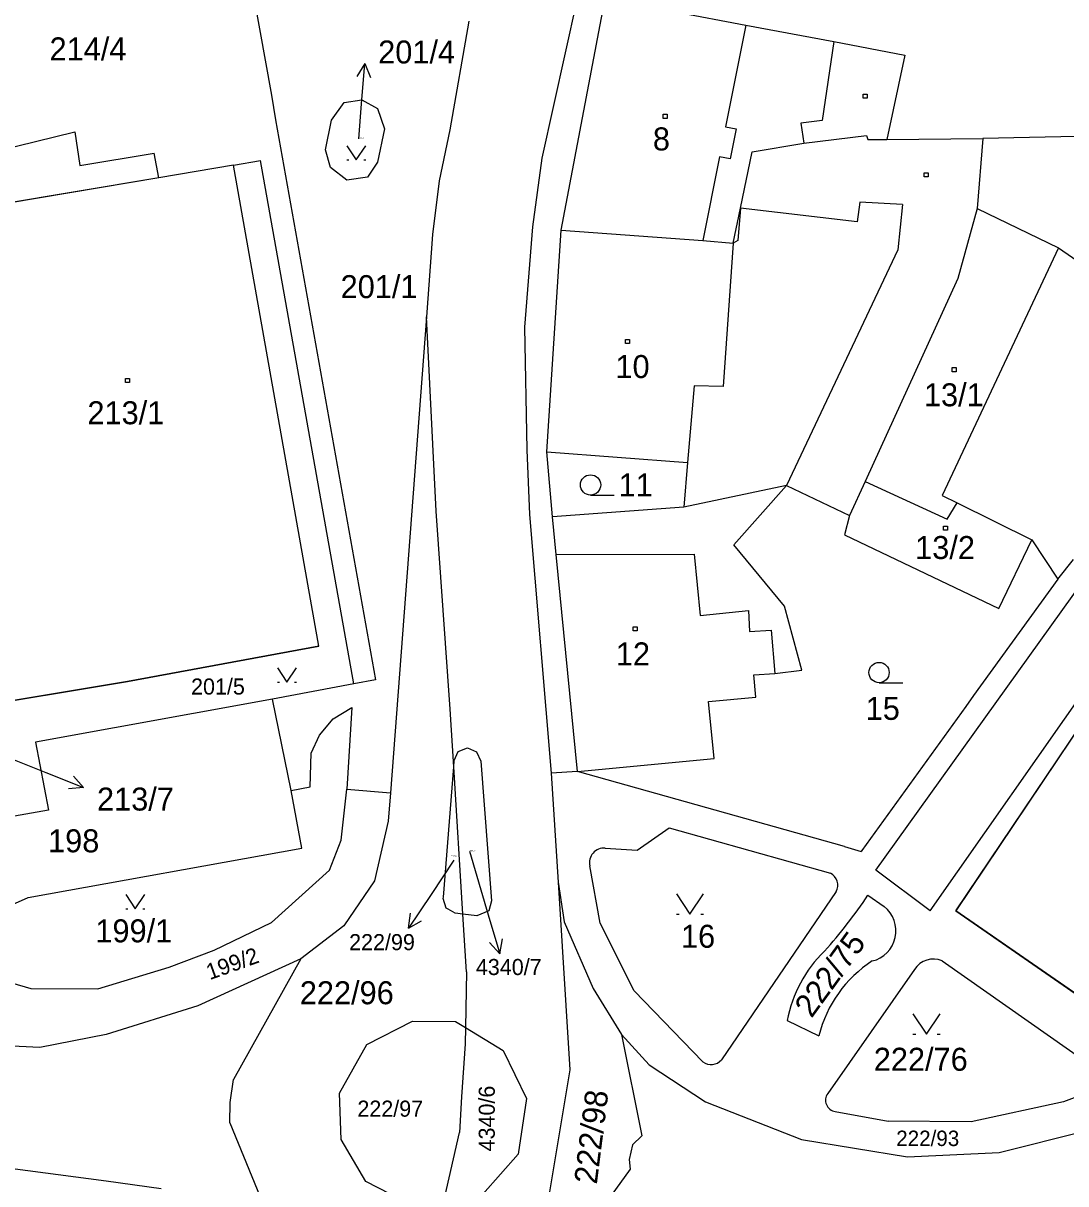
# Model space of a CAD drawing. Extents: x -468021 to -466942, y -1130484 to -1128584.
# Drawn here: x -467492.3 to -467415.1, y -1129055.3 to -1128969.4 of the extents above; entities that cross this region are included whole.
import ezdxf

# ---------------------------------------------------------------- set-up
doc = ezdxf.new("R2010")
doc.units = 0
for name, color, linetype in [('19-PK-šrafy', 7, 'Continuous'), ('22-Odběrná místa-šrafy', 7, 'Continuous'), ('DKM', 7, 'Continuous')]:
    doc.layers.add(name, color=color, linetype=linetype)

msp = doc.modelspace()

# ---------------------------------------------------------------- linework, layer by layer
at = {"layer": '19-PK-šrafy'}
msp.add_lwpolyline([(-467399.25, -1129024.07), (-467400.13, -1129023.43), (-467410.43, -1129016.03), (-467423.26, -1129035.1), (-467412.19, -1129042.78), (-467399.25, -1129024.07)], dxfattribs=at)
at = {"layer": '22-Odběrná místa-šrafy'}
msp.add_lwpolyline([(-467512.86, -1129016.55), (-467503.64, -1129015.36), (-467503.25, -1129018.31), (-467503.09, -1129019.57), (-467497.18, -1129018.69), (-467496.9, -1129020.2), (-467484.57, -1129018.14), (-467470.42, -1129015.53), (-467476.73, -1128979.94), (-467482.25, -1128980.87), (-467497.8, -1128983.49), (-467504.8, -1128984.67), (-467508.2, -1128985.12), (-467508.09, -1128985.96), (-467516.57, -1128987.04), (-467515.48, -1128993.37), (-467516.56, -1128993.53)], close=True, dxfattribs=at)
at = {"layer": 'DKM'}
for p, q in [((-467475.84, -1128964.15), (-467473.92, -1128974.77)), ((-467451.33, -1128967.74), (-467453.9, -1128979.43)), ((-467452.49, -1128984.74), (-467449.21, -1128967.58)), ((-467449.21, -1128967.58), (-467438.81, -1128969.59)), ((-467459.31, -1128969.29), (-467460.71, -1128977.34)), ((-467438.81, -1128969.59), (-467440.31, -1128977.11)), ((-467438.81, -1128969.59), (-467432.3, -1128970.79)), ((-467432.3, -1128970.79), (-467433.17, -1128976.65)), ((-467432.3, -1128970.79), (-467427.04, -1128971.8)), ((-467467.019, -1128972.418), (-467467.594, -1128973.377)), ((-467467.25, -1128975.41), (-467467.019, -1128972.418)), ((-467467.019, -1128972.418), (-467466.597, -1128973.454)), ((-467427.04, -1128971.8), (-467428.37, -1128978.04)), ((-467473.92, -1128974.77), (-467473.62, -1128976.6)), ((-467430.13, -1128974.68), (-467429.83, -1128974.68)), ((-467430.13, -1128974.98), (-467430.13, -1128974.68)), ((-467429.83, -1128974.98), (-467430.13, -1128974.98)), ((-467429.83, -1128974.68), (-467429.83, -1128974.98)), ((-467469.48, -1128976.61), (-467468.54, -1128975.31)), ((-467468.54, -1128975.31), (-467467.22, -1128975.1)), ((-467467.45, -1128977.99), (-467467.25, -1128975.41)), ((-467467.22, -1128975.1), (-467466.08, -1128975.74)), ((-467466.08, -1128975.74), (-467465.56, -1128977.25)), ((-467473.62, -1128976.6), (-467466.23, -1129018.01)), ((-467469.93, -1128978.8), (-467469.48, -1128976.61)), ((-467444.93, -1128976.18), (-467444.63, -1128976.18)), ((-467444.93, -1128976.48), (-467444.93, -1128976.18)), ((-467444.63, -1128976.48), (-467444.93, -1128976.48)), ((-467444.63, -1128976.18), (-467444.63, -1128976.48)), ((-467433.17, -1128976.65), (-467434.74, -1128976.83)), ((-467498.32, -1128979.89), (-467488.47, -1128977.47)), ((-467488.47, -1128977.47), (-467488.11, -1128979.96)), ((-467465.56, -1128977.25), (-467466.06, -1128979.71)), ((-467460.71, -1128977.34), (-467461.5, -1128981.11)), ((-467440.31, -1128977.11), (-467439.53, -1128977.26)), ((-467439.53, -1128977.26), (-467439.96, -1128979.48)), ((-467434.74, -1128976.83), (-467434.51, -1128978.32)), ((-467438.34, -1128978.96), (-467434.51, -1128978.32)), ((-467434.51, -1128978.32), (-467429.88, -1128977.75)), ((-467429.88, -1128977.75), (-467429.78, -1128978.05)), ((-467429.78, -1128978.05), (-467428.37, -1128978.04)), ((-467428.37, -1128978.04), (-467421.28, -1128977.96)), ((-467421.28, -1128977.96), (-467421.69, -1128983.15)), ((-467409.89, -1128977.74), (-467421.28, -1128977.96)), ((-467488.11, -1128979.96), (-467482.61, -1128979.06)), ((-467482.25, -1128980.87), (-467482.61, -1128979.06)), ((-467469.56, -1128980.11), (-467469.93, -1128978.8)), ((-467468.34, -1128978.51), (-467467.64, -1128979.56)), ((-467467.64, -1128979.56), (-467466.94, -1128978.51)), ((-467440.75, -1128979.32), (-467441.99, -1128985.51)), ((-467439.96, -1128979.48), (-467440.75, -1128979.32)), ((-467439.21, -1128983.12), (-467438.34, -1128978.96)), ((-467476.73, -1128979.94), (-467482.25, -1128980.87)), ((-467476.73, -1128979.94), (-467474.72, -1128979.6)), ((-467470.42, -1129015.53), (-467476.73, -1128979.94)), ((-467467.83, -1129018.31), (-467474.72, -1128979.6)), ((-467468.33, -1128981.05), (-467469.56, -1128980.11)), ((-467468.34, -1128979.56), (-467468.2, -1128979.56)), ((-467467.08, -1128979.56), (-467466.94, -1128979.56)), ((-467466.06, -1128979.71), (-467466.82, -1128980.83)), ((-467453.9, -1128979.43), (-467454.61, -1128984.51)), ((-467482.25, -1128980.87), (-467497.8, -1128983.49)), ((-467466.82, -1128980.83), (-467468.33, -1128981.05)), ((-467425.61, -1128980.51), (-467425.31, -1128980.51)), ((-467425.61, -1128980.81), (-467425.61, -1128980.51)), ((-467425.31, -1128980.81), (-467425.61, -1128980.81)), ((-467425.31, -1128980.51), (-467425.31, -1128980.81)), ((-467461.5, -1128981.11), (-467462, -1128985.08)), ((-467430.38, -1128982.69), (-467430.56, -1128984.13)), ((-467427.21, -1128982.86), (-467430.38, -1128982.69)), ((-467439.76, -1128985.72), (-467439.21, -1128983.12)), ((-467439.21, -1128983.12), (-467439.41, -1128985.52)), ((-467430.56, -1128984.13), (-467439.21, -1128983.12)), ((-467427.21, -1128982.86), (-467427.57, -1128986.2)), ((-467421.69, -1128983.15), (-467423.11, -1128988.33)), ((-467421.69, -1128983.15), (-467415.68, -1128986.06)), ((-467462, -1128985.08), (-467462.45, -1128991.16)), ((-467454.61, -1128984.51), (-467455.19, -1128991.92)), ((-467453.53, -1129001.16), (-467452.49, -1128984.74)), ((-467452.49, -1128984.74), (-467441.99, -1128985.51)), ((-467441.99, -1128985.51), (-467439.76, -1128985.72)), ((-467439.76, -1128985.72), (-467440.5, -1128996.32)), ((-467439.41, -1128985.52), (-467439.76, -1128985.72)), ((-467427.57, -1128986.2), (-467435.8, -1129003.63)), ((-467415.68, -1128986.06), (-467424.29, -1129004.37)), ((-467415.68, -1128986.06), (-467403.02, -1128994.78)), ((-467423.11, -1128988.33), (-467429.99, -1129003.34)), ((-467462.45, -1128991.16), (-467465.11, -1129026.37)), ((-467461.73, -1129005.55), (-467462.45, -1128991.16)), ((-467455.19, -1128991.92), (-467455.03, -1129001)), ((-467447.71, -1128992.83), (-467447.41, -1128992.83)), ((-467447.71, -1128993.13), (-467447.71, -1128992.83)), ((-467447.41, -1128992.83), (-467447.41, -1128993.13)), ((-467447.41, -1128993.13), (-467447.71, -1128993.13)), ((-467423.54, -1128994.92), (-467423.24, -1128994.92)), ((-467423.54, -1128995.22), (-467423.54, -1128994.92)), ((-467423.24, -1128995.22), (-467423.54, -1128995.22)), ((-467423.24, -1128994.92), (-467423.24, -1128995.22)), ((-467484.72, -1128995.73), (-467484.42, -1128995.73)), ((-467484.72, -1128996.03), (-467484.72, -1128995.73)), ((-467484.42, -1128996.03), (-467484.72, -1128996.03)), ((-467484.42, -1128995.73), (-467484.42, -1128996.03)), ((-467442.63, -1128996.26), (-467443.12, -1129001.94)), ((-467440.5, -1128996.32), (-467442.63, -1128996.26)), ((-467455.03, -1129001), (-467454.83, -1129005.78)), ((-467453.53, -1129001.16), (-467443.12, -1129001.94)), ((-467453.11, -1129005.96), (-467453.53, -1129001.16)), ((-467443.12, -1129001.94), (-467443.41, -1129005.24)), ((-467429.99, -1129003.34), (-467431.14, -1129005.85)), ((-467429.99, -1129003.34), (-467423.9, -1129006.13)), ((-467435.8, -1129003.63), (-467443.41, -1129005.24)), ((-467439.71, -1129008.02), (-467435.8, -1129003.63)), ((-467435.8, -1129003.63), (-467431.14, -1129005.85)), ((-467450.3, -1129004.35), (-467448.55, -1129004.35)), ((-467424.29, -1129004.37), (-467423.17, -1129004.92)), ((-467423.9, -1129006.13), (-467423.17, -1129004.92)), ((-467423.17, -1129004.92), (-467417.64, -1129007.65)), ((-467460.69, -1129020.19), (-467461.73, -1129005.55)), ((-467454.83, -1129005.78), (-467453.22, -1129024.92)), ((-467443.41, -1129005.24), (-467453.11, -1129005.96)), ((-467452.84, -1129008.75), (-467453.11, -1129005.96)), ((-467431.14, -1129005.85), (-467431.5, -1129007.29)), ((-467424.18, -1129006.64), (-467423.88, -1129006.64)), ((-467424.18, -1129006.94), (-467424.18, -1129006.64)), ((-467423.88, -1129006.64), (-467423.88, -1129006.94)), ((-467431.5, -1129007.29), (-467420.09, -1129012.74)), ((-467423.88, -1129006.94), (-467424.18, -1129006.94)), ((-467420.09, -1129012.74), (-467417.64, -1129007.65)), ((-467417.64, -1129007.65), (-467415.73, -1129010.56)), ((-467435.94, -1129012.58), (-467439.71, -1129008.02)), ((-467452.84, -1129008.75), (-467442.63, -1129008.71)), ((-467451.28, -1129024.81), (-467452.84, -1129008.75)), ((-467442.63, -1129008.71), (-467442.19, -1129013.26)), ((-467415.73, -1129010.56), (-467414.57, -1129009.12)), ((-467429.2, -1129032.11), (-467413.85, -1129010.73)), ((-467415.73, -1129010.56), (-467421.96, -1129019.19)), ((-467434.66, -1129017.31), (-467435.94, -1129012.58)), ((-467442.19, -1129013.26), (-467438.61, -1129012.89)), ((-467438.61, -1129012.89), (-467438.53, -1129014.45)), ((-467447.15, -1129014.09), (-467446.85, -1129014.09)), ((-467447.15, -1129014.39), (-467447.15, -1129014.09)), ((-467446.85, -1129014.39), (-467447.15, -1129014.39)), ((-467446.85, -1129014.09), (-467446.85, -1129014.39)), ((-467438.53, -1129014.45), (-467436.93, -1129014.35)), ((-467436.93, -1129014.35), (-467436.67, -1129017.55)), ((-467470.42, -1129015.53), (-467484.57, -1129018.14)), ((-467425.18, -1129035.1), (-467411.44, -1129015.51)), ((-467423.26, -1129035.1), (-467410.43, -1129016.03)), ((-467473.47, -1129017.14), (-467472.77, -1129018.19)), ((-467472.77, -1129018.19), (-467472.07, -1129017.14)), ((-467438.22, -1129017.65), (-467436.67, -1129017.55)), ((-467438.06, -1129019.29), (-467438.22, -1129017.65)), ((-467436.67, -1129017.55), (-467434.66, -1129017.31)), ((-467484.57, -1129018.14), (-467496.9, -1129020.2)), ((-467467.83, -1129018.31), (-467473.83, -1129019.44)), ((-467473.47, -1129018.19), (-467473.33, -1129018.19)), ((-467472.21, -1129018.19), (-467472.07, -1129018.19)), ((-467466.23, -1129018.01), (-467467.83, -1129018.31)), ((-467428.95, -1129018.23), (-467427.2, -1129018.23)), ((-467473.83, -1129019.44), (-467491.39, -1129022.64)), ((-467472.47, -1129026.21), (-467473.83, -1129019.44)), ((-467441.57, -1129019.63), (-467438.06, -1129019.29)), ((-467441.16, -1129023.83), (-467441.57, -1129019.63)), ((-467421.96, -1129019.19), (-467422.54, -1129020)), ((-467469.35, -1129020.91), (-467467.97, -1129020.06)), ((-467467.97, -1129020.06), (-467468.35, -1129026.12)), ((-467460.43, -1129024.45), (-467460.69, -1129020.19)), ((-467422.54, -1129020), (-467430.22, -1129030.64)), ((-467470.37, -1129022.11), (-467469.35, -1129020.91)), ((-467470.97, -1129023.45), (-467470.37, -1129022.11)), ((-467495.16, -1129023.07), (-467490.62, -1129024.88)), ((-467491.39, -1129022.64), (-467490.42, -1129027.65)), ((-467460.09, -1129023.33), (-467459.4, -1129023.06)), ((-467459.4, -1129023.06), (-467458.75, -1129023.34)), ((-467471.05, -1129025.94), (-467470.97, -1129023.45)), ((-467460.43, -1129024.45), (-467460.39, -1129023.98)), ((-467460.39, -1129023.98), (-467460.09, -1129023.33)), ((-467458.75, -1129023.34), (-467458.43, -1129024.04)), ((-467451.28, -1129024.81), (-467441.16, -1129023.83)), ((-467461.19, -1129034.1), (-467460.43, -1129024.45)), ((-467459.75, -1129035.35), (-467460.43, -1129024.45)), ((-467458.43, -1129024.04), (-467457.63, -1129034.38)), ((-467451.28, -1129024.81), (-467453.22, -1129024.92)), ((-467431.52, -1129030.35), (-467451.28, -1129024.81)), ((-467490.62, -1129024.88), (-467487.833, -1129025.99)), ((-467487.833, -1129025.99), (-467488.576, -1129025.155)), ((-467453.22, -1129024.92), (-467452.71, -1129033)), ((-467487.833, -1129025.99), (-467488.947, -1129026.084)), ((-467472.47, -1129026.21), (-467471.05, -1129025.94)), ((-467471.68, -1129030.48), (-467472.47, -1129026.21)), ((-467468.75, -1129029.87), (-467468.35, -1129026.12)), ((-467468.35, -1129026.12), (-467465.11, -1129026.37)), ((-467465.11, -1129026.37), (-467465.27, -1129028.48)), ((-467490.42, -1129027.65), (-467494.46, -1129028.36)), ((-467465.27, -1129028.48), (-467466.29, -1129032.89)), ((-467446.85, -1129030.61), (-467444.48, -1129028.96)), ((-467444.48, -1129028.96), (-467432.55, -1129032.33)), ((-467469.62, -1129032.11), (-467468.75, -1129029.87)), ((-467491.93, -1129034.13), (-467471.68, -1129030.48)), ((-467459.25, -1129030.7), (-467457.87, -1129035.4)), ((-467449.21, -1129030.48), (-467446.85, -1129030.61)), ((-467431.52, -1129030.35), (-467430.28, -1129030.73)), ((-467430.22, -1129030.64), (-467430.28, -1129030.73)), ((-467460.42, -1129031.37), (-467462.11, -1129033.9)), ((-467473.92, -1129035.96), (-467469.62, -1129032.11)), ((-467449.58, -1129036.01), (-467450.35, -1129031.79)), ((-467425.18, -1129035.1), (-467429.2, -1129032.11)), ((-467466.29, -1129032.89), (-467468.57, -1129036.23)), ((-467452.71, -1129033), (-467451.84, -1129046.87)), ((-467452.71, -1129033), (-467452.25, -1129035.92)), ((-467495.6, -1129035.76), (-467491.93, -1129034.13)), ((-467484.7, -1129033.91), (-467484, -1129034.96)), ((-467484, -1129034.96), (-467483.3, -1129033.91)), ((-467462.11, -1129033.9), (-467463.778, -1129036.393)), ((-467461.2, -1129034.2), (-467461.19, -1129034.1)), ((-467460.99, -1129034.9), (-467461.2, -1129034.2)), ((-467443.95, -1129033.85), (-467442.95, -1129035.35)), ((-467442.95, -1129035.35), (-467441.95, -1129033.85)), ((-467432.13, -1129033.69), (-467440.61, -1129046.13)), ((-467429.77, -1129033.95), (-467428.57, -1129034.8)), ((-467484.7, -1129034.96), (-467484.56, -1129034.96)), ((-467483.44, -1129034.96), (-467483.3, -1129034.96)), ((-467460.85, -1129034.98), (-467460.99, -1129034.9)), ((-467460.33, -1129035.27), (-467460.85, -1129034.98)), ((-467457.83, -1129035.12), (-467458.72, -1129035.48)), ((-467457.63, -1129034.38), (-467457.83, -1129035.12)), ((-467412.19, -1129042.78), (-467423.26, -1129035.1)), ((-467478.17, -1129038.02), (-467473.92, -1129035.96)), ((-467463.778, -1129036.393), (-467463.637, -1129035.283)), ((-467463.778, -1129036.393), (-467462.806, -1129035.84)), ((-467459.75, -1129035.35), (-467460.33, -1129035.27)), ((-467458.72, -1129035.48), (-467459.75, -1129035.35)), ((-467459.49, -1129039.62), (-467459.75, -1129035.35)), ((-467457.87, -1129035.4), (-467457.026, -1129038.279)), ((-467452.25, -1129035.92), (-467450.11, -1129040.85)), ((-467447.07, -1129041.03), (-467449.58, -1129036.01)), ((-467443.95, -1129035.35), (-467443.75, -1129035.35)), ((-467442.15, -1129035.35), (-467441.95, -1129035.35)), ((-467468.57, -1129036.23), (-467471.74, -1129038.65)), ((-467457.026, -1129038.279), (-467457.787, -1129037.459)), ((-467457.026, -1129038.279), (-467456.828, -1129037.178)), ((-467481.49, -1129039.28), (-467478.17, -1129038.02)), ((-467497.27, -1129039.25), (-467491.74, -1129040.85)), ((-467486.78, -1129040.89), (-467481.49, -1129039.28)), ((-467471.74, -1129038.65), (-467479.37, -1129042.13)), ((-467471.74, -1129038.65), (-467476.73, -1129047.58)), ((-467426.32, -1129039.46), (-467432.75, -1129048.63)), ((-467424.28, -1129038.81), (-467411.49, -1129047.8)), ((-467459.49, -1129039.62), (-467459.57, -1129043.75)), ((-467491.74, -1129040.85), (-467486.78, -1129040.89)), ((-467450.11, -1129040.85), (-467448.02, -1129044.25)), ((-467441.99, -1129046.27), (-467447.07, -1129041.03)), ((-467479.37, -1129042.13), (-467486.14, -1129044.25)), ((-467426.44, -1129042.74), (-467425.44, -1129044.24)), ((-467425.44, -1129044.24), (-467424.44, -1129042.74)), ((-467466.86, -1129045), (-467463.47, -1129043.26)), ((-467463.47, -1129043.26), (-467460.3, -1129043.3)), ((-467460.3, -1129043.3), (-467459.57, -1129043.75)), ((-467459.57, -1129043.75), (-467459.59, -1129044.94)), ((-467459.57, -1129043.75), (-467456.78, -1129045.45)), ((-467435.75, -1129043.23), (-467433.4, -1129044.36)), ((-467486.14, -1129044.25), (-467491.07, -1129045.23)), ((-467448.02, -1129044.25), (-467445.96, -1129046.51)), ((-467448.02, -1129044.25), (-467446.5, -1129051.75)), ((-467426.44, -1129044.24), (-467426.24, -1129044.24)), ((-467424.64, -1129044.24), (-467424.44, -1129044.24)), ((-467491.07, -1129045.23), (-467493.61, -1129045.09)), ((-467468.89, -1129048.6), (-467466.86, -1129045)), ((-467459.59, -1129044.94), (-467459.86, -1129048.87)), ((-467456.78, -1129045.45), (-467455.04, -1129048.99)), ((-467451.84, -1129046.87), (-467454.66, -1129063.71)), ((-467445.96, -1129046.51), (-467441.79, -1129049.24)), ((-467476.97, -1129049.29), (-467476.73, -1129047.58)), ((-467411.49, -1129047.8), (-467415.3, -1129049.24)), ((-467468.77, -1129052.02), (-467468.89, -1129048.6)), ((-467459.86, -1129048.87), (-467460, -1129051.5)), ((-467476.99, -1129050.8), (-467476.97, -1129049.29)), ((-467455.04, -1129048.99), (-467455.65, -1129053.11)), ((-467441.79, -1129049.24), (-467434.7, -1129052.03)), ((-467415.3, -1129049.24), (-467422.14, -1129050.72)), ((-467432.2, -1129049.96), (-467428.27, -1129050.68)), ((-467476.99, -1129050.8), (-467473.5, -1129059.29)), ((-467422.14, -1129050.72), (-467428.27, -1129050.68)), ((-467420.07, -1129052.99), (-467413.77, -1129051.4)), ((-467486.14, -1129055.12), (-467508.06, -1129052.24)), ((-467466.94, -1129055.14), (-467468.77, -1129052.02)), ((-467461.22, -1129056.82), (-467460, -1129051.5)), ((-467446.5, -1129051.75), (-467447.21, -1129052.43)), ((-467434.7, -1129052.03), (-467426.84, -1129053.32)), ((-467455.65, -1129053.11), (-467458.27, -1129056.06)), ((-467447.21, -1129052.43), (-467447.45, -1129053.51)), ((-467426.84, -1129053.32), (-467420.07, -1129052.99)), ((-467447.45, -1129053.51), (-467447.36, -1129054.22)), ((-467447.36, -1129054.22), (-467453.09, -1129062.13)), ((-467482.08, -1129055.67), (-467486.14, -1129055.12)), ((-467463.24, -1129057.03), (-467466.94, -1129055.14))]:
    msp.add_line(p, q, dxfattribs=at)
for centre in [(-467450.3, -1129003.6), (-467428.95, -1129017.48)]:
    msp.add_circle(centre, 0.75, dxfattribs=at)
for centre, radius, start, end in [((-467449.318, -1129031.537), 1.063, 84.16296, 193.77556), ((-467432.979, -1129033.207), 0.976, 330.36691, 63.95693), ((-467459.968, -1129013.843), 36.28, 318.04062, 326.34335), ((-467429.986, -1129036.595), 2.286, 283.30787, 51.72507), ((-467426.386, -1129044.961), 9.523, 133.90956, 169.5289), ((-467424.45, -1129046.554), 9.215, 122.93449, 166.22529), ((-467424.93, -1129040.297), 1.623, 66.40618, 148.94043), ((-467441.373, -1129045.477), 1.005, 232.14874, 319.43685), ((-467432.066, -1129049.126), 0.845, 144.08862, 260.84488)]:
    msp.add_arc(centre, radius, start, end, dxfattribs=at)

# ---------------------------------------------------------------- texts
for s, height, p in [('214/4', 1.7, (-467490.34, -1128972.19)), ('201/4', 1.7, (-467466.02, -1128972.42)), ('8', 1.7, (-467445.69, -1128978.85)), ('201/4', 0.1, (-467467.45, -1128977.99)), ('201/1', 1.7, (-467468.8, -1128989.78)), ('10', 1.7, (-467448.46, -1128995.69)), ('13/1', 1.7, (-467425.63, -1128997.78)), ('213/1', 1.7, (-467487.54, -1128999.11)), ('11', 1.7, (-467448.23, -1129004.45)), ('13/2', 1.7, (-467426.28, -1129009.08)), ('12', 1.7, (-467448.43, -1129016.95)), ('201/5', 1.19, (-467479.87, -1129019.11)), ('15', 1.7, (-467429.94, -1129020.98)), ('213/7', 1.7, (-467486.83, -1129027.69)), ('198', 1.7, (-467490.45, -1129030.78)), ('4340/7', 0.1, (-467459.25, -1129030.7)), ('222/99', 0.1, (-467460.65, -1129031.11)), ('199/1', 1.7, (-467486.95, -1129037.44)), ('222/99', 1.19, (-467468.171, -1129038.02)), ('16', 1.7, (-467443.61, -1129037.84)), ('4340/7', 1.19, (-467458.79, -1129039.86)), ('222/96', 1.7, (-467471.82, -1129042.02)), ('222/76', 1.7, (-467429.34, -1129046.94)), ('222/97', 1.19, (-467467.56, -1129050.34)), ('222/93', 1.14, (-467427.68, -1129052.51))]:
    msp.add_text(s, height=height, dxfattribs=at).set_placement(p)
for s, height, rotation, p in [('222/75', 1.7, 54, (-467433.947, -1129043.104)), ('199/2', 1.19, 19.6605, (-467478.49, -1129040.24)), ('4340/6', 1.19, 90, (-467457.39, -1129052.91)), ('222/98', 1.7, 82.83789, (-467449.84, -1129055.38))]:
    msp.add_text(s, height=height, rotation=rotation, dxfattribs=at).set_placement(p)

doc.saveas('drawing.dxf')
